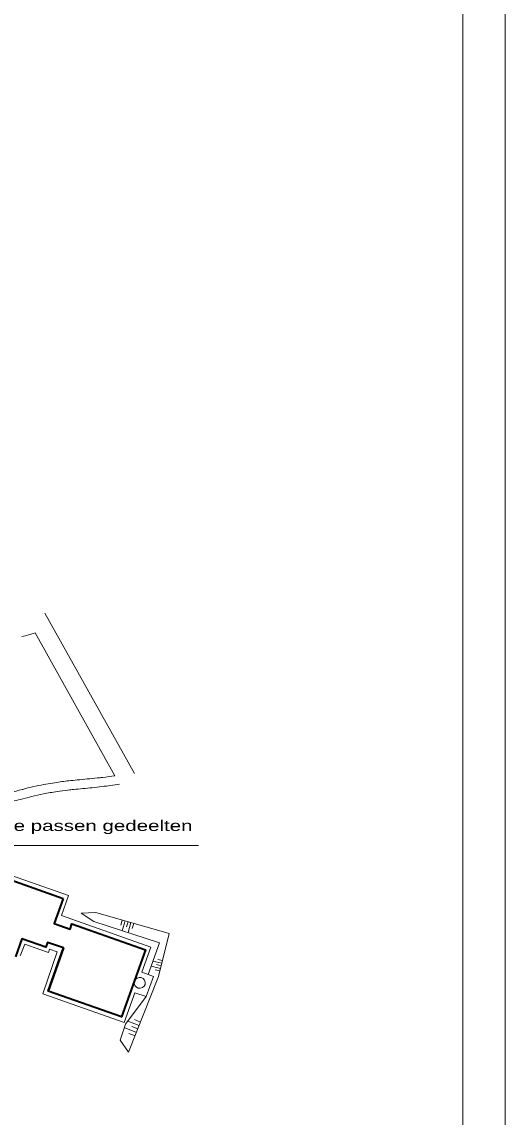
# Model space of a CAD drawing. Extents: x 295824 to 414724, y 24924 to 109024.
# Drawn here: x 403291 to 414724, y 57152 to 83088 of the extents above; entities that cross this region are included whole.
import ezdxf

# ---------------------------------------------------------------- set-up
doc = ezdxf.new("R2010")
doc.units = 0
doc.header["$LTSCALE"] = 100
for name, color, linetype, lineweight in [('1', 7, 'Continuous', 13), ('19', 7, 'Continuous', 13), ('24', 7, 'Continuous', 13), ('25', 7, 'Continuous', 13), ('26', 7, 'Continuous', 13), ('4', 7, 'Continuous', 35), ('51', 7, 'Continuous', 13)]:
    doc.layers.add(name, color=color, linetype=linetype, lineweight=lineweight)

msp = doc.modelspace()

# ---------------------------------------------------------------- linework, layer by layer
at = {"layer": '1'}
msp.add_line((414723.6, 24923.8), (414723.6, 109023.8), dxfattribs=at)
msp.add_lwpolyline([(304995.6, 25923.8), (413723.6, 25923.8), (413723.6, 108023.8), (304995.6, 108023.8)], dxfattribs=at)
at = {"layer": '19'}
msp.add_line((404266.6, 62331.9), (401403.2, 63344.3), dxfattribs=at)
msp.add_lwpolyline([(403913.8, 60135.6), (405648.1, 59522.8), (406212, 61115.7)], dxfattribs=at)
at = {"layer": '24'}
msp.add_line((395432.7, 63582.1), (407470.1, 63582.1), dxfattribs=at)
at = {"layer": '25'}
msp.add_line((406542.8, 61276.2), (406276.7, 60526.1), dxfattribs=at)
for points in [[(406771.5, 61499.4), (405041.8, 61995.1), (404696, 61980.7), (404993.5, 61781), (406542.8, 61276.2)], [(406231.8, 60004.3), (405745.2, 59352.3), (405613, 58972.4), (405816.2, 58692.5), (406190, 59641.2), (406473.5, 60360.4), (406520.7, 60480.3), (406771.5, 61499.4)]]:
    msp.add_lwpolyline(points, dxfattribs=at)
at = {"layer": '26'}
for p, q in [((405633.4, 61698.2), (405667.1, 61815.9)), ((405666.9, 61561.2), (405734.4, 61796.6)), ((405767.8, 61659.7), (405801.6, 61777.3)), ((405801.3, 61522.7), (405868.8, 61758)), ((405902.3, 61621.1), (405936, 61738.8)), ((406348.4, 60728.3), (406568.4, 60674.3)), ((406390.7, 60847.5), (406598.6, 60796.4)), ((406476.5, 60761.7), (406583.5, 60735.4)), ((406506.6, 60884), (406613.7, 60857.6)), ((406446.4, 60639.3), (406553.4, 60613.1)), ((405799.7, 59425.3), (406063.9, 59321.2)), ((405953, 59459.5), (406096.2, 59403)), ((405713, 59270.5), (405999.4, 59157.6)), ((405888.6, 59295.9), (406031.7, 59239.4)), ((405824, 59132.2), (405967.2, 59075.8))]:
    msp.add_line(p, q, dxfattribs=at)
at = {"layer": '4'}
msp.add_line((404272.5, 61157), (403913.8, 60135.6), dxfattribs=at)
for points in [[(398345.9, 64959.9), (398438.8, 64927), (401183.2, 63954), (401049.6, 63577.2), (400968.8, 63343.5), (401353.9, 63204.8), (401403.2, 63344.3), (404266.6, 62331.9)], [(404266.6, 62331.9), (404053.5, 61732.4), (404431.3, 61599.1), (404475.9, 61728.5), (406212, 61115.7)], [(404431.3, 61599.1), (404475.9, 61728.5), (406212, 61115.7), (405648.1, 59522.8), (403913.8, 60135.6), (404272.5, 61157), (403897, 61288.9), (403856.6, 61173.8), (403292.1, 61376.1), (403138.8, 60943.5)]]:
    msp.add_lwpolyline(points, dxfattribs=at)
at = {"layer": '4', "lineweight": 13}
for centre, start, end in [((406080.1, 60329.5), 29.64, 208.17622), ((406079.1, 60331.4), 209.13476, 28.68146)]:
    msp.add_arc(centre, 130, start, end, dxfattribs=at)
at = {"layer": '51'}
for p, q in [((403835.2, 69084.5), (405952.6, 65286.3)), ((405491.3, 65232), (403602.9, 68621.1)), ((401439.3, 63439), (404392.5, 62396.9)), ((403356.9, 61244.5), (403252, 60966.7)), ((403711.8, 61119), (403356.9, 61244.5))]:
    msp.add_line(p, q, dxfattribs=at)
for points in [[(406342.9, 61176.8), (404225.7, 61925.8), (404392.5, 62396.9)], [(403784.5, 60071.2), (404128.5, 61063), (403945.2, 61127.1), (403923.5, 61045.9), (403711.8, 61119)], [(406342.9, 61176.8), (406131.7, 60582.3), (406276.7, 60526.1)], [(406276.7, 60526.1), (406401, 60481.6), (406231.8, 60004.3), (405959.6, 60094.2), (405710.4, 59391.2), (403784.5, 60071.2)]]:
    msp.add_lwpolyline(points, dxfattribs=at)
for centre, radius, start, end in [((403017.9, 70107.6), 1597.5, 279.85146, 291.48171), ((405140, 58399.2), 6757.2, 96.27081, 99.10473), ((405780.3, 52571.9), 12619.6, 95.37354, 96.27081), ((397541.4, 140162.6), 75357.8, 275.37354, 275.74072), ((404428.2, 71658.5), 6508.4, 275.74072, 276.81483), ((400746.6, 102465.5), 37534.6, 276.81483, 277.26209), ((401652.9, 71090), 6395.7, 282.34377, 284.86156), ((401652.9, 71090), 6395.7, 284.86156, 285.60827), ((404348.9, 61439.6), 3624.2, 101.27121, 105.60827), ((405900.1, 53656), 11561, 99.10473, 101.27121), ((405721.9, 54480.7), 10503, 98.75261, 100.55259), ((405103.7, 58495.8), 6440.6, 96.45394, 98.75261), ((405192.3, 57712.1), 7229.3, 95.37081, 96.45394), ((397502.3, 139509.1), 74928.4, 275.37081, 275.70725), ((404150.3, 72989.8), 8077.7, 275.70725, 277.36407), ((401844.6, 90830.2), 26066.5, 277.36407, 278.28636), ((401537.4, 71907.7), 7435.1, 282.17071, 285.46087), ((404410.4, 61520.6), 3342, 100.55259, 105.46087)]:
    msp.add_arc(centre, radius, start, end, dxfattribs=at)

# ---------------------------------------------------------------- texts
at = {"layer": '24', "width": 1.45}
msp.add_text('aan te passen gedeelten', height=250, dxfattribs=at).set_placement((402017.3, 63928.4))

doc.saveas('drawing.dxf')
